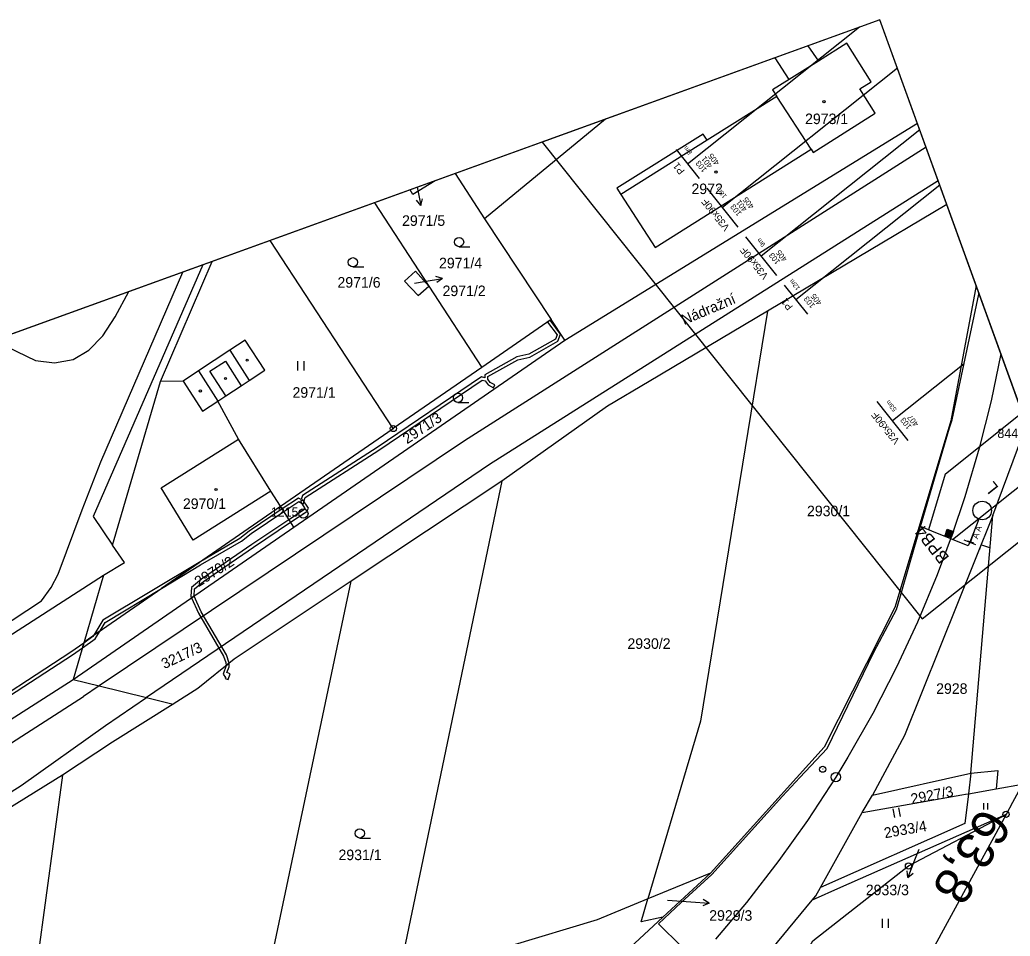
# Model space of a CAD drawing. Extents: x -620552 to -620056, y -1123312 to -1122890.
# Drawn here: x -620295.9 to -620136.2, y -1123037.5 to -1122889.6 of the extents above; entities that cross this region are included whole.
import ezdxf

# ---------------------------------------------------------------- set-up
doc = ezdxf.new("R2010")
doc.units = 0
for name, color, linetype in [('HranDP', 7, 'Continuous'), ('Hranice parcel', 7, 'Continuous'), ('Parcelní čísla', 7, 'Continuous'), ('Pop  PČ popisy', 7, 'Continuous'), ('Rámečky', 7, 'Continuous'), ('Rámečky-tisk', 7, 'Continuous'), ('Vnitřní kresba', 7, 'Continuous'), ('Vrstva 1', 7, 'Continuous'), ('Vrstva 2', 7, 'Continuous'), ('Vrstva 3', 7, 'Continuous'), ('Vrstva 33', 7, 'Continuous'), ('Vrstva 6', 7, 'Continuous'), ('Vrstva 7', 7, 'Continuous'), ('Věcná břemena k části', 7, 'Continuous'), ('Značky bodu BP', 7, 'Continuous'), ('Značky budov', 7, 'Continuous'), ('Značky kultur', 7, 'Continuous')]:
    doc.layers.add(name, color=color, linetype=linetype)

msp = doc.modelspace()

# ---------------------------------------------------------------- linework, layer by layer
at = {"layer": 'HranDP'}
for p, q in [((-620160.04, -1123017.49), (-620158.39, -1123014.71)), ((-620166.78, -1123029.59), (-620160.04, -1123017.49)), ((-620184.51, -1123027.31), (-620192.2, -1123034.39)), ((-620192.2, -1123034.39), (-620197.49, -1123039.27))]:
    msp.add_line(p, q, dxfattribs=at)
for points in [[(-620141.66, -1122932.48), (-620145.74, -1122954.29), (-620154.8, -1122984.44), (-620166.17, -1123006.98), (-620184.51, -1123027.31)], [(-620139.01, -1122969.61), (-620134.15, -1122956.58), (-620133.7, -1122954.48)], [(-620139.01, -1122969.61), (-620153.24, -1123005.09), (-620158.39, -1123014.71)], [(-620168.12, -1123031.65), (-620167.55, -1123030.97), (-620166.78, -1123029.59)], [(-620243.96, -1123098.03), (-620228.02, -1123087.3), (-620208.81, -1123075.27), (-620182.41, -1123048.95), (-620179.31, -1123045.19), (-620168.12, -1123031.65)]]:
    msp.add_lwpolyline(points, dxfattribs=at)
at = {"layer": 'Hranice parcel'}
for p, q in [((-620208, -1122941.31), (-620151.16, -1122906.27)), ((-620225.71, -1122914.41), (-620220.99, -1122921.7)), ((-620146.4, -1122919.39), (-620175.35, -1122936.6)), ((-620220.99, -1122921.7), (-620210.21, -1122937.96)), ((-620235.69, -1122955.55), (-620255.53, -1122925.21)), ((-620273.22, -1122947.97), (-620264.92, -1122928.61)), ((-620210.21, -1122937.96), (-620221.39, -1122945.68)), ((-620208, -1122941.31), (-620210.21, -1122937.96)), ((-620251.74, -1122971.48), (-620208, -1122941.31)), ((-620221.39, -1122945.68), (-620235.69, -1122955.55)), ((-620201.16, -1122951.94), (-620218.17, -1122964.05)), ((-620253.87, -1122968.1), (-620235.69, -1122955.55)), ((-620218.17, -1122964.05), (-620242.46, -1122980.18)), ((-620218.17, -1122964.05), (-620234.98, -1123044.6)), ((-620285.54, -1122989.95), (-620253.87, -1122968.1)), ((-620251.74, -1122971.48), (-620253.87, -1122968.1)), ((-620142.51, -1123011.15), (-620139.01, -1122969.61)), ((-620287.33, -1122996.04), (-620251.74, -1122971.48)), ((-620369, -1123034.76), (-620282.4, -1122979.23)), ((-620282.4, -1122979.23), (-620285.54, -1122989.95)), ((-620263.28, -1123078.74), (-620242.46, -1122980.18)), ((-620285.54, -1122989.95), (-620287.33, -1122996.04)), ((-620280.96, -1123006.18), (-620289.02, -1123011.5)), ((-620289.02, -1123011.5), (-620330.98, -1123037.45)), ((-620158.39, -1123014.71), (-620142.51, -1123011.15)), ((-620142.51, -1123011.15), (-620142.91, -1123014.47)), ((-620138.43, -1123013.68), (-620134.2, -1123012.93)), ((-620160.04, -1123017.49), (-620158.39, -1123014.71)), ((-620142.91, -1123014.47), (-620138.43, -1123013.68)), ((-620166.78, -1123029.59), (-620160.04, -1123017.49)), ((-620152.59, -1123026.13), (-620136.85, -1123017.81)), ((-620136.85, -1123017.81), (-620148.96, -1123040.16)), ((-620184.51, -1123027.31), (-620194.62, -1123031.45)), ((-620184.51, -1123027.31), (-620192.2, -1123034.39)), ((-620192.2, -1123034.39), (-620197.49, -1123039.27))]:
    msp.add_line(p, q, dxfattribs=at)
for points in [[(-620168.81, -1122893.81), (-620167.12, -1122896.26), (-620171.85, -1122899.25), (-620174.08, -1122895.72)], [(-620198.98, -1122917.79), (-620193.45, -1122926.35), (-620168.27, -1122910.5), (-620173.85, -1122901.99), (-620185.06, -1122909.04), (-620185.7, -1122908.03), (-620199.62, -1122916.78), (-620198.98, -1122917.79)], [(-620201.44, -1122905.62), (-620220.99, -1122921.7)], [(-620228.95, -1122915.59), (-620232.52, -1122917.77), (-620232.97, -1122917.04)], [(-620238.74, -1122919.13), (-620229.95, -1122932.57), (-620221.39, -1122945.68)], [(-620229.95, -1122932.57), (-620232.13, -1122930.14), (-620233.86, -1122931.77)], [(-620233.86, -1122931.77), (-620231.67, -1122934.08), (-620229.95, -1122932.57)], [(-620141.66, -1122932.48), (-620145.74, -1122954.29), (-620154.8, -1122984.44), (-620166.17, -1123006.98), (-620184.51, -1123027.31)], [(-620175.35, -1122936.6), (-620194.44, -1122947.94), (-620201.16, -1122951.94)], [(-620175.35, -1122936.6), (-620186.12, -1123002.76), (-620194.62, -1123031.45)], [(-620253.87, -1122968.1), (-620255.41, -1122965.65), (-620260.66, -1122957.29), (-620263.97, -1122951.11), (-620262.72, -1122950.29), (-620260.22, -1122948.64), (-620258.93, -1122947.79), (-620256.43, -1122946.15), (-620259.56, -1122941.28), (-620262.06, -1122942.93), (-620267.1, -1122946.24), (-620269.6, -1122947.89), (-620273.22, -1122947.97)], [(-620282.4, -1122979.23), (-620279.03, -1122977.17), (-620280.97, -1122974.36), (-620273.22, -1122947.97)], [(-620139.01, -1122969.61), (-620134.15, -1122956.58), (-620133.7, -1122954.48)], [(-620139.01, -1122969.61), (-620153.24, -1123005.09), (-620158.39, -1123014.71)], [(-620242.46, -1122980.18), (-620261.36, -1122992.76), (-620267.21, -1122997.48)], [(-620365.22, -1123044.99), (-620354.45, -1123039), (-620287.33, -1122996.04)], [(-620267.21, -1122997.48), (-620271.2, -1123000), (-620280.96, -1123006.18)], [(-620289.02, -1123011.5), (-620293.05, -1123041.17), (-620295.61, -1123091.1), (-620294.3, -1123096.22)], [(-620134.2, -1123012.93), (-620135.79, -1123015.87), (-620136.85, -1123017.81)], [(-620142.91, -1123014.47), (-620143.48, -1123019.27), (-620166.78, -1123029.59)], [(-620160.04, -1123017.49), (-620143.96, -1123014.65), (-620143.4, -1123014.55), (-620142.91, -1123014.47)], [(-620136.85, -1123017.81), (-620163.54, -1123029.62), (-620168.12, -1123031.65)], [(-620169.42, -1123054.19), (-620174.5, -1123049.57), (-620168, -1123038.2), (-620152.59, -1123026.13)], [(-620168.12, -1123031.65), (-620167.55, -1123030.97), (-620166.78, -1123029.59)], [(-620243.96, -1123098.03), (-620228.02, -1123087.3), (-620208.81, -1123075.27), (-620182.41, -1123048.95), (-620179.31, -1123045.19), (-620168.12, -1123031.65)], [(-620194.62, -1123031.45), (-620202.81, -1123034.81), (-620216.72, -1123039.04), (-620234.98, -1123044.6)], [(-620192.2, -1123034.39), (-620195.73, -1123035.14), (-620194.62, -1123031.45)]]:
    msp.add_lwpolyline(points, dxfattribs=at)
at = {"layer": 'Pop  PČ popisy'}
for p, q in [((-620231.83, -1122916.63), (-620231.26, -1122919.57)), ((-620231.26, -1122919.57), (-620231.94, -1122918.68)), ((-620231.26, -1122919.57), (-620230.96, -1122918.49)), ((-620232.28, -1122932.09), (-620230.7, -1122931.83)), ((-620230.7, -1122931.83), (-620227.74, -1122931.36)), ((-620227.74, -1122931.36), (-620228.8, -1122931.02)), ((-620227.74, -1122931.36), (-620228.65, -1122932.01)), ((-620150.94, -1123023.48), (-620151.6, -1123025.22)), ((-620151.6, -1123025.22), (-620152.68, -1123028.02)), ((-620152.68, -1123028.02), (-620152.78, -1123026.91)), ((-620152.68, -1123028.02), (-620151.85, -1123027.27)), ((-620191.47, -1123031.65), (-620187.72, -1123031.92)), ((-620187.72, -1123031.92), (-620184.73, -1123032.13)), ((-620184.73, -1123032.13), (-620185.76, -1123032.56)), ((-620184.73, -1123032.13), (-620185.69, -1123031.56))]:
    msp.add_line(p, q, dxfattribs=at)
at = {"layer": 'Rámečky'}
for p, q in [((-620157.19, -1122889.6), (-620552.1, -1123032.6)), ((-620056.07, -1123168.86), (-620157.19, -1122889.6))]:
    msp.add_line(p, q, dxfattribs=at)
at = {"layer": 'Rámečky-tisk'}
for points in [[(-620450.98, -1123311.85), (-620056.07, -1123168.86), (-620157.19, -1122889.6), (-620552.1, -1123032.6)], [(-620128.51, -1122968.81), (-620157.19, -1122889.6), (-620211.7, -1122909.34)], [(-620211.7, -1122909.34), (-620150.41, -1122986.26), (-620128.51, -1122968.81)]]:
    msp.add_lwpolyline(points, dxfattribs=at)
at = {"layer": 'Vnitřní kresba'}
for p, q in [((-620162.51, -1122893.37), (-620167.12, -1122896.26)), ((-620158.59, -1122899.61), (-620162.51, -1122893.37)), ((-620171.85, -1122899.25), (-620174.52, -1122900.92)), ((-620160.44, -1122900.76), (-620158.59, -1122899.61)), ((-620174.52, -1122900.92), (-620173.85, -1122901.99)), ((-620157.94, -1122904.69), (-620160.44, -1122900.76)), ((-620167.95, -1122911), (-620157.94, -1122904.69)), ((-620185.06, -1122909.04), (-620198.98, -1122917.79)), ((-620149.74, -1122910.17), (-620224.19, -1122957.54)), ((-620168.27, -1122910.5), (-620167.95, -1122911)), ((-620147.79, -1122915.57), (-620220.18, -1122961.38)), ((-620266.41, -1122929.15), (-620284.09, -1122969.72)), ((-620282.88, -1122960.95), (-620269.65, -1122930.32)), ((-620280.53, -1122937.51), (-620278.32, -1122933.46)), ((-620282.53, -1122940.57), (-620280.53, -1122937.51)), ((-620300.01, -1122941.39), (-620293.37, -1122944.55)), ((-620284.77, -1122942.9), (-620282.53, -1122940.57)), ((-620287.32, -1122944.4), (-620284.77, -1122942.9)), ((-620262.06, -1122942.93), (-620258.93, -1122947.79)), ((-620293.37, -1122944.55), (-620290.35, -1122944.97)), ((-620290.35, -1122944.97), (-620287.32, -1122944.4)), ((-620265.27, -1122946.29), (-620262.76, -1122944.66)), ((-620262.76, -1122944.66), (-620260.22, -1122948.64)), ((-620267.1, -1122946.24), (-620263.97, -1122951.11)), ((-620262.72, -1122950.29), (-620265.27, -1122946.29)), ((-620269.6, -1122947.89), (-620266.47, -1122952.75)), ((-620266.47, -1122952.75), (-620263.97, -1122951.11)), ((-620273.13, -1122965.13), (-620260.66, -1122957.29)), ((-620224.19, -1122957.54), (-620283.1, -1122997.08)), ((-620285.84, -1122968.66), (-620282.88, -1122960.95)), ((-620220.18, -1122961.38), (-620275.49, -1122998.97)), ((-620267.97, -1122973.56), (-620273.13, -1122965.13)), ((-620255.41, -1122965.65), (-620267.97, -1122973.56)), ((-620289.73, -1122979.06), (-620285.84, -1122968.66)), ((-620284.09, -1122969.72), (-620280.97, -1122974.36)), ((-620290.87, -1122981.21), (-620289.73, -1122979.06)), ((-620292.44, -1122983.33), (-620290.87, -1122981.21)), ((-620307.51, -1122993.27), (-620292.44, -1122983.33)), ((-620287.33, -1122996.04), (-620283.1, -1122997.08)), ((-620283.1, -1122997.08), (-620285.65, -1122998.79)), ((-620283.1, -1122997.08), (-620275.49, -1122998.97)), ((-620336.04, -1123031.13), (-620285.65, -1122998.79)), ((-620282.13, -1123003.48), (-620275.49, -1122998.97)), ((-620275.49, -1122998.97), (-620271.2, -1123000)), ((-620295.72, -1123013.16), (-620282.13, -1123003.48)), ((-620142.51, -1123011.15), (-620138.18, -1123010.74)), ((-620138.18, -1123010.74), (-620138.43, -1123013.68)), ((-620339.98, -1123041.29), (-620295.72, -1123013.16))]:
    msp.add_line(p, q, dxfattribs=at)
at = {"layer": 'Vrstva 1'}
for p, q in [((-620148.83, -1122972.09), (-620150.63, -1122971.37)), ((-620142.94, -1122974.46), (-620148.83, -1122972.09)), ((-620142.71, -1122973.89), (-620142.94, -1122974.46))]:
    msp.add_line(p, q, dxfattribs=at)
for points in [[(-620150.63, -1122971.37), (-620145.98, -1122955.43), (-620145.54, -1122954.13), (-620141.24, -1122933.85), (-620141.21, -1122933.72)], [(-620137.67, -1122943.51), (-620139.25, -1122951.1), (-620141.18, -1122958.74), (-620143.49, -1122966.59), (-620145.52, -1122972.66), (-620147.96, -1122979.17), (-620151.13, -1122986.8), (-620154.5, -1122994.08), (-620158.35, -1123001.53), (-620162.37, -1123008.6), (-620164.31, -1123011.8), (-620168.88, -1123018.81), (-620173.5, -1123025.27), (-620178.73, -1123032.03), (-620183.71, -1123037.93)], [(-620302.99, -1123100.7), (-620292.4, -1123098.24), (-620281.7, -1123095.56), (-620261.93, -1123088.35), (-620253.64, -1123085.66), (-620236.13, -1123076.73), (-620225.47, -1123069.74), (-620216.19, -1123063.28), (-620205.15, -1123054.34), (-620198.59, -1123048.78), (-620192.32, -1123042.45), (-620189.21, -1123039.13), (-620192.93, -1123035.47), (-620189.24, -1123032.05), (-620184.32, -1123027.49), (-620172.92, -1123014.85), (-620170.12, -1123011.86), (-620165.72, -1123007.16), (-620158.18, -1122991.64), (-620154.53, -1122984.74), (-620154, -1122982.93), (-620152.3, -1122977.09), (-620150.63, -1122971.37)]]:
    msp.add_lwpolyline(points, dxfattribs=at)
at = {"layer": 'Vrstva 2'}
for p, q in [((-620141.25, -1122970.17), (-620142.71, -1122973.89)), ((-620146.28, -1122971.83), (-620145.68, -1122973.09)), ((-620146.62, -1122972.63), (-620146.51, -1122972.86)), ((-620146.56, -1122972.45), (-620146.34, -1122972.92)), ((-620146.5, -1122972.28), (-620146.16, -1122972.98)), ((-620146.44, -1122972.1), (-620145.99, -1122973.05)), ((-620146.38, -1122971.93), (-620145.81, -1122973.11)), ((-620146.1, -1122971.89), (-620145.61, -1122972.92)), ((-620145.93, -1122971.95), (-620145.55, -1122972.74)), ((-620145.75, -1122972.02), (-620145.49, -1122972.57)), ((-620145.58, -1122972.08), (-620145.43, -1122972.39)), ((-620145.4, -1122972.14), (-620145.37, -1122972.22)), ((-620143.65, -1122973.53), (-620141.78, -1122974.26))]:
    msp.add_line(p, q, dxfattribs=at)
msp.add_lwpolyline([(-620145.35, -1122972.16), (-620145.7, -1122973.15), (-620146.69, -1122972.8), (-620146.34, -1122971.81)], close=True, dxfattribs=at)
msp.add_lwpolyline([(-620145.35, -1122972.16), (-620145.7, -1122973.15), (-620146.69, -1122972.8), (-620146.34, -1122971.81)], close=True, dxfattribs=at)
msp.add_circle((-620140.7, -1122968.78), 1.5, dxfattribs=at)
at = {"layer": 'Vrstva 33'}
for p, q in [((-620160.5, -1122890.8), (-620188.21, -1122912.87)), ((-620154.36, -1122897.42), (-620182.6, -1122919.91)), ((-620150.77, -1122907.34), (-620176.37, -1122927.73)), ((-620190.08, -1122910.53), (-620186.34, -1122915.22)), ((-620185.09, -1122916.78), (-620180.11, -1122923.04)), ((-620147.53, -1122916.27), (-620170.76, -1122934.77)), ((-620178.86, -1122924.61), (-620173.88, -1122930.86)), ((-620172.63, -1122932.43), (-620168.89, -1122937.12)), ((-620143.63, -1122945.12), (-620155.19, -1122954.33)), ((-620157.68, -1122951.2), (-620152.69, -1122957.46)), ((-620146.7, -1122962.91), (-620134.24, -1122952.98)), ((-620145.47, -1122973.44), (-620131.01, -1122961.91)), ((-620146.7, -1122962.91), (-620149.37, -1122971.88))]:
    msp.add_line(p, q, dxfattribs=at)
at = {"layer": 'Vrstva 6'}
for p, q in [((-620141.96, -1122971.97), (-620142.59, -1122973.84)), ((-620143.06, -1122973.69), (-620142.12, -1122974))]:
    msp.add_line(p, q, dxfattribs=at)
at = {"layer": 'Vrstva 7'}
msp.add_line((-620166.39, -1123010.47), (-620166.44, -1123010.56), dxfattribs=at)
for centre, radius in [((-620166.42, -1123010.52), 0.5), ((-620164.31, -1123011.8), 0.75)]:
    msp.add_circle(centre, radius, dxfattribs=at)
at = {"layer": 'Věcná břemena k části'}
for points in [[(-620220.85, -1122947.88), (-620220.38, -1122948.48), (-620219.54, -1122948.96), (-620219.3, -1122948.52), (-620220.04, -1122948.1), (-620220.45, -1122947.58), (-620220.43, -1122947.18), (-620215.58, -1122944.45), (-620213.67, -1122944.01), (-620209.12, -1122941.46), (-620208.72, -1122940.34), (-620210.39, -1122938.08), (-620210.8, -1122938.37), (-620209.28, -1122940.42), (-620209.52, -1122941.12), (-620213.85, -1122943.53), (-620215.76, -1122943.97), (-620220.91, -1122946.88), (-620220.94, -1122947.35), (-620221.44, -1122947.23), (-620238.3, -1122958.63), (-620250.35, -1122966.38), (-620250.52, -1122967.01), (-620250.96, -1122966.76), (-620253.6, -1122968.53), (-620258.92, -1122972.11), (-620260.46, -1122973.29), (-620267, -1122977.16), (-620273.08, -1122981.36), (-620266.78, -1122977.55), (-620260.18, -1122973.71), (-620258.62, -1122972.51), (-620253.33, -1122968.95), (-620250.94, -1122967.34), (-620250.2, -1122967.75), (-620249.91, -1122966.7), (-620238.02, -1122959.05), (-620221.34, -1122947.77)], [(-620267.76, -1122981.44), (-620266.3, -1122980.23), (-620258.21, -1122974.67), (-620252.25, -1122970.68), (-620249.64, -1122968.93), (-620249.36, -1122968.41), (-620250.25, -1122967.05), (-620250.66, -1122967.34), (-620249.94, -1122968.43), (-620250.02, -1122968.59), (-620252.51, -1122970.26), (-620258.49, -1122974.25), (-620266.6, -1122979.83), (-620268.24, -1122981.19), (-620268.35, -1122982.6), (-620268.23, -1122982.86), (-620267.82, -1122982.58)], [(-620282.15, -1122986.83), (-620273.08, -1122981.36), (-620267, -1122977.16), (-620282.51, -1122986.47), (-620283.97, -1122988.87), (-620282.96, -1122988.17)], [(-620262.66, -1122993.81), (-620262.17, -1122993.41), (-620262.59, -1122992.04), (-620266.69, -1122985.11), (-620267.82, -1122982.58), (-620268.23, -1122982.86), (-620267.13, -1122985.33), (-620263.05, -1122992.26), (-620262.67, -1122993.31)], [(-620283.75, -1122989.47), (-620282.96, -1122988.17), (-620283.97, -1122988.87), (-620284.13, -1122989.13), (-620285.6, -1122990.17), (-620285.83, -1122990.94)], [(-620359.12, -1123037.46), (-620340.69, -1123026.08), (-620322.75, -1123014.93), (-620304.43, -1123003.11), (-620287.42, -1122992.06), (-620285.83, -1122990.94), (-620285.6, -1122990.17), (-620287.7, -1122991.64), (-620304.71, -1123002.69), (-620323.01, -1123014.51), (-620340.95, -1123025.66), (-620359.38, -1123037.04), (-620368.18, -1123042.28), (-620367.79, -1123042.63)], [(-620262.66, -1122993.81), (-620263.14, -1122995.17), (-620262.74, -1122995.71), (-620262.81, -1122995.9), (-620262.34, -1122996.07), (-620262, -1122995.13), (-620262.52, -1122994.94), (-620262.16, -1122994.01), (-620262.17, -1122993.41)]]:
    msp.add_lwpolyline(points, close=True, dxfattribs=at)
at = {"layer": 'Značky bodu BP'}
for centre, radius in [((-620235.69, -1122955.55), 0.5), ((-620235.69, -1122955.55), 0.0303), ((-620250.19, -1122969.27), 0.75), ((-620250.19, -1122969.27), 0.03), ((-620136.85, -1123017.81), 0.5), ((-620136.85, -1123017.81), 0.0303), ((-620152.59, -1123026.13), 0.5), ((-620152.59, -1123026.13), 0.0303)]:
    msp.add_circle(centre, radius, dxfattribs=at)
at = {"layer": 'Značky budov'}
for centre in [(-620166.23, -1122902.81), (-620183.64, -1122914.16), (-620259.26, -1122944.53), (-620262.75, -1122947.47), (-620266.8, -1122949.49), (-620264.28, -1122965.39)]:
    msp.add_circle(centre, 0.175, dxfattribs=at)
at = {"layer": 'Značky kultur'}
for p, q in [((-620225.08, -1122926.21), (-620223.33, -1122926.21)), ((-620242.2, -1122929.48), (-620240.45, -1122929.48)), ((-620251.08, -1122946.18), (-620251.08, -1122944.68)), ((-620250.08, -1122946.18), (-620250.08, -1122944.68)), ((-620225.25, -1122951.34), (-620223.5, -1122951.34)), ((-620140.44, -1123017.02), (-620140.44, -1123016.02)), ((-620139.77, -1123017.02), (-620139.77, -1123016.02)), ((-620154.8, -1123018.32), (-620155.05, -1123016.94)), ((-620153.88, -1123018.16), (-620154.12, -1123016.77)), ((-620241.1, -1123021.62), (-620239.35, -1123021.62)), ((-620156.8, -1123036.14), (-620156.8, -1123034.64)), ((-620155.8, -1123036.14), (-620155.8, -1123034.64))]:
    msp.add_line(p, q, dxfattribs=at)
for centre in [(-620225.08, -1122925.46), (-620242.2, -1122928.73), (-620225.25, -1122950.59), (-620241.1, -1123020.87)]:
    msp.add_circle(centre, 0.75, dxfattribs=at)

# ---------------------------------------------------------------- texts
at = {"layer": 'Parcelní čísla'}
for s, p in [('2973/1', (-620169.27, -1122906.43)), ('2972', (-620187.59, -1122917.72)), ('2971/5', (-620234.27, -1122922.85)), ('2971/4', (-620228.31, -1122929.7)), ('2971/6', (-620244.69, -1122932.82)), ('2971/2', (-620227.74, -1122934.18)), ('2971/1', (-620251.94, -1122950.58)), ('2970/1', (-620269.62, -1122968.53)), ('2930/1', (-620168.96, -1122969.7)), ('2930/2', (-620197.92, -1122991.1)), ('2928', (-620148.13, -1122998.36)), ('2931/1', (-620244.52, -1123025.19)), ('2933/3', (-620159.47, -1123030.85)), ('2929/3', (-620184.73, -1123034.97))]:
    msp.add_text(s, height=1.7, dxfattribs=at).set_placement(p)
for s, rotation, p in [('2971/3', 34, (-620233.45, -1122958.11)), ('2970/2', 32, (-620267.08, -1122981.16)), ('3217/3', 25, (-620272.61, -1122994.39)), ('2927/3', 11, (-620152.05, -1123016.19)), ('2933/4', 10, (-620156.38, -1123021.67))]:
    msp.add_text(s, height=1.7, rotation=rotation, dxfattribs=at).set_placement(p)
at = {"layer": 'Pop  PČ popisy'}
msp.add_text('Nádražní', height=1.7, rotation=23, dxfattribs=at).set_placement((-620188.79, -1122938.87))
at = {"layer": 'Vrstva 3'}
for s, p in [('L', (-620137.97, -1122965.09)), ('BPB4', (-620145.92, -1122976.33))]:
    msp.add_text(s, height=2, rotation=128.542, dxfattribs=at).set_placement(p)
at = {"layer": 'Vrstva 33'}
for s, height, p in [('8m', 0.75, (-620187.46, -1122911)), ('P1', 1.15, (-620188.61, -1122913.98)), ('103', 0.9, (-620185.06, -1122913.78)), ('401', 0.9, (-620184.14, -1122913.09)), ('405', 0.9, (-620183.03, -1122912.63)), ('18m', 0.75, (-620181.86, -1122918.04)), ('V35x90F', 1.15, (-620181.35, -1122923.08)), ('401', 0.9, (-620178.53, -1122920.13)), ('405', 0.9, (-620177.43, -1122919.67)), ('103', 0.9, (-620179.45, -1122920.82)), ('9m', 0.75, (-620175.62, -1122925.86)), ('V35x90F', 1.15, (-620175.12, -1122930.9)), ('405', 0.9, (-620172.1, -1122928.2)), ('103', 0.9, (-620173.22, -1122928.64)), ('12m', 0.75, (-620170.02, -1122932.9)), ('P1', 1.15, (-620171.16, -1122935.88)), ('103', 0.9, (-620167.61, -1122935.68)), ('405', 0.9, (-620166.49, -1122935.24)), ('53m', 0.75, (-620154.44, -1122952.45)), ('V35x90F', 1.15, (-620153.94, -1122957.5)), ('103', 0.9, (-620152.03, -1122955.23)), ('407', 0.9, (-620150.9, -1122954.81))]:
    msp.add_text(s, height=height, rotation=128.542, dxfattribs=at).set_placement(p)
at = {"layer": 'Vrstva 6'}
for s, height, rotation, p in [('  A A ', 1, 71.5027, (-620141.64, -1122974.16)), ('L', 1.5, 251.5027, (-620140.85, -1122974.05))]:
    msp.add_text(s, height=height, rotation=rotation, dxfattribs=at).set_placement(p)
at = {"layer": 'Vrstva 7'}
msp.add_text('63,8', height=6, rotation=238.7026, dxfattribs=at).set_placement((-620140.84, -1123016.42))
at = {"layer": 'Značky bodu BP'}
for s, p in [('844', (-620138.25, -1122957.08)), ('1215', (-620255.44, -1122969.77))]:
    msp.add_text(s, height=1.5, dxfattribs=at).set_placement(p)

doc.saveas('drawing.dxf')
